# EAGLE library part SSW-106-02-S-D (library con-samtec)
THROUGH-HOLE .025" SQ POST SOCKET Source: Samtec SSW.pdf
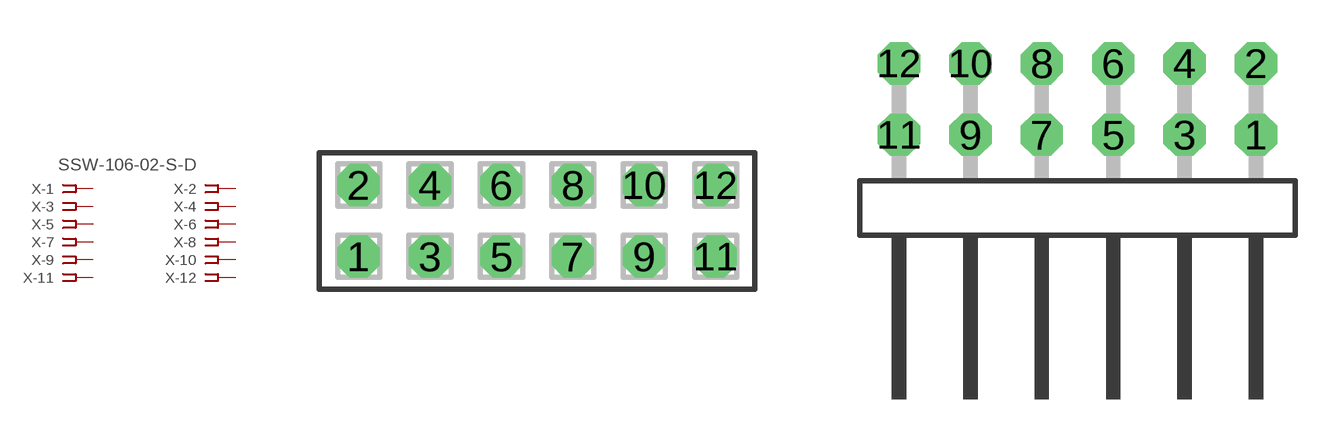
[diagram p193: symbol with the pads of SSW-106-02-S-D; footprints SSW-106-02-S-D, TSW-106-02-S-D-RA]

Designator prefix X; gates -1=FPINV -2=FPIN -3=FPIN -4=FPIN -5=FPIN -6=FPIN -7=FPIN -8=FPIN -9=FPIN -10=FPIN -11=FPIN -12=FPIN

## SSW-106-02-S-D (MPN: SSW-106-02-S-D; OC_FARNELL: unknown; OC_NEWARK: 11P9414)  [SSW-106-02-S-D]
1  -1:1  pas
2  -2:1  pas
3  -3:1  pas
4  -4:1  pas
5  -5:1  pas
6  -6:1  pas
7  -7:1  pas
8  -8:1  pas
9  -9:1  pas
10  -10:1  pas
11  -11:1  pas
12  -12:1  pas

## SSW-106-02-S-D-RA (MPN: SSW-106-02-S-D-RA; OC_FARNELL: unknown; OC_NEWARK: 11P9415)  [TSW-106-02-S-D-RA]
Pads as for SSW-106-02-S-D

## Footprint SSW-106-02-S-D (pad centres in mm)
THROUGH-HOLE .025" SQ POST SOCKET Source: Samtec SSW.pdf
drill 1 pad 1.5 octagon: 1 -6.35,-1.27; 2 -6.35,1.27; 3 -3.81,-1.27; 4 -3.81,1.27; 5 -1.27,-1.27; 6 -1.27,1.27; 7 1.27,-1.27; 8 1.27,1.27; 9 3.81,-1.27; 10 3.81,1.27; 11 6.35,-1.27; 12 6.35,1.27

## Footprint TSW-106-02-S-D-RA (pad centres in mm)
THROUGH-HOLE .025" SQ POST HEADER Source: Samtec TSW.pdf
drill 1 pad 1.5 octagon: 1 6.35,1.524; 2 6.35,4.064; 3 3.81,1.524; 4 3.81,4.064; 5 1.27,1.524; 6 1.27,4.064; 7 -1.27,1.524; 8 -1.27,4.064; 9 -3.81,1.524; 10 -3.81,4.064; 11 -6.35,1.524; 12 -6.35,4.064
